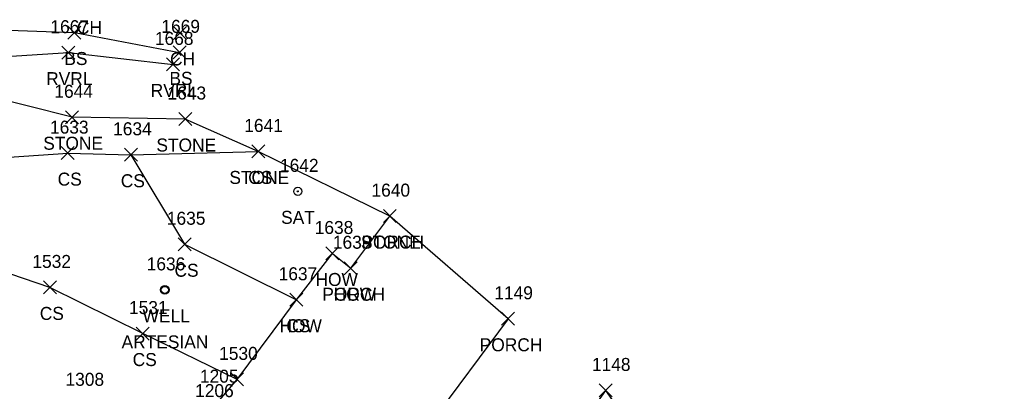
# Model space of a CAD drawing. Extents: x 1537342 to 1542195, y 163002 to 168596.
# Drawn here: x 1541938.8 to 1542089.8, y 163294.7 to 163351.9 of the extents above; entities that cross this region are included whole.
import ezdxf

# ---------------------------------------------------------------- set-up
doc = ezdxf.new("R2010")
doc.units = 0
for name, color, linetype in [('L_A', 7, 'Continuous'), ('L_I', 7, 'Continuous'), ('L_TIC', 7, 'Continuous'), ('LANT', 7, 'Continuous'), ('LASF', 7, 'Continuous'), ('LAWA', 7, 'Continuous'), ('LAWE', 7, 'Continuous'), ('LBC', 7, 'Continuous'), ('LBF', 7, 'Continuous'), ('LELB', 7, 'Continuous'), ('R_I', 7, 'Continuous'), ('U_A', 7, 'Continuous'), ('U_C', 7, 'Continuous'), ('U_I', 7, 'Continuous'), ('UWW', 7, 'Continuous')]:
    doc.layers.add(name, color=color, linetype=linetype)

msp = doc.modelspace()

# ---------------------------------------------------------------- linework, layer by layer
at = {"layer": 'L_TIC'}
for points in [[(1541946.26, 163348.87), (1541948.26, 163350.87)], [(1541948.26, 163348.87), (1541946.26, 163350.87)], [(1541962.52, 163348.81), (1541964.52, 163350.81)], [(1541964.52, 163348.81), (1541962.52, 163350.81)], [(1541945.35, 163345.77), (1541947.35, 163347.77)], [(1541947.35, 163345.77), (1541945.35, 163347.77)], [(1541962.47, 163345.82), (1541964.47, 163347.82)], [(1541964.47, 163345.82), (1541962.47, 163347.82)], [(1541961.46, 163343.96), (1541963.46, 163345.96)], [(1541963.46, 163343.96), (1541961.46, 163345.96)], [(1541945.91, 163335.83), (1541947.91, 163337.83)], [(1541947.91, 163335.83), (1541945.91, 163337.83)], [(1541963.35, 163335.56), (1541965.35, 163337.56)], [(1541965.35, 163335.56), (1541963.35, 163337.56)], [(1541945.24, 163330.31), (1541947.24, 163332.31)], [(1541947.24, 163330.31), (1541945.24, 163332.31)], [(1541954.97, 163330.06), (1541956.97, 163332.06)], [(1541956.97, 163330.06), (1541954.97, 163332.06)], [(1541954.97, 163330.06), (1541956.97, 163332.06)], [(1541956.97, 163330.06), (1541954.97, 163332.06)], [(1541974.61, 163330.57), (1541976.61, 163332.57)], [(1541976.61, 163330.57), (1541974.61, 163332.57)], [(1541974.61, 163330.57), (1541976.61, 163332.57)], [(1541976.61, 163330.57), (1541974.61, 163332.57)], [(1541994.88, 163320.62), (1541996.88, 163322.62)], [(1541996.88, 163320.62), (1541994.88, 163322.62)], [(1541994.88, 163320.62), (1541996.88, 163322.62)], [(1541996.88, 163320.62), (1541994.88, 163322.62)], [(1541994.88, 163320.62), (1541996.88, 163322.62)], [(1541996.88, 163320.62), (1541994.88, 163322.62)], [(1541963.25, 163316.29), (1541965.25, 163318.29)], [(1541965.25, 163316.29), (1541963.25, 163318.29)], [(1541986.04, 163314.87), (1541988.04, 163316.87)], [(1541988.04, 163314.87), (1541986.04, 163316.87)], [(1541988.85, 163312.6), (1541990.85, 163314.6)], [(1541990.85, 163312.6), (1541988.85, 163314.6)], [(1541988.85, 163312.6), (1541990.85, 163314.6)], [(1541990.85, 163312.6), (1541988.85, 163314.6)], [(1541942.49, 163309.65), (1541944.49, 163311.65)], [(1541944.49, 163309.65), (1541942.49, 163311.65)], [(1541980.48, 163307.75), (1541982.48, 163309.75)], [(1541982.48, 163307.75), (1541980.48, 163309.75)], [(1541980.48, 163307.75), (1541982.48, 163309.75)], [(1541982.48, 163307.75), (1541980.48, 163309.75)], [(1542013.11, 163304.82), (1542015.11, 163306.82)], [(1542015.11, 163304.82), (1542013.11, 163306.82)], [(1542013.11, 163304.82), (1542015.11, 163306.82)], [(1542015.11, 163304.82), (1542013.11, 163306.82)], [(1541956.8, 163302.55), (1541958.8, 163304.55)], [(1541958.8, 163302.55), (1541956.8, 163304.55)], [(1541971.35, 163295.5), (1541973.35, 163297.5)], [(1541973.35, 163295.5), (1541971.35, 163297.5)], [(1541971.35, 163295.5), (1541973.35, 163297.5)], [(1541973.35, 163295.5), (1541971.35, 163297.5)], [(1541971.35, 163295.5), (1541973.35, 163297.5)], [(1541973.35, 163295.5), (1541971.35, 163297.5)], [(1542028.16, 163293.8), (1542030.16, 163295.8)], [(1542030.16, 163293.8), (1542028.16, 163295.8)], [(1542028.16, 163293.8), (1542030.16, 163295.8)], [(1542030.16, 163293.8), (1542028.16, 163295.8)]]:
    msp.add_lwpolyline(points, dxfattribs=at)
at = {"layer": 'LANT'}
for radius in [0.625, 0.0833]:
    msp.add_circle((1541981.69, 163325.43), radius, dxfattribs=at)
at = {"layer": 'LASF'}
msp.add_lwpolyline([(1541995.88, 163321.62), (1541975.61, 163331.57), (1541964.35, 163336.56), (1541946.91, 163336.83), (1541932.97, 163340.32), (1541930.29, 163345.76)], dxfattribs=at)
at = {"layer": 'LAWA'}
msp.add_lwpolyline([(1542191.37, 163069.26), (1542155.13, 163097.46), (1542123.95, 163126.28), (1542083.78, 163159.16), (1542082.85, 163172.31), (1542083.05, 163192.11), (1542078.54, 163207.24), (1542059.97, 163213.12), (1542055.91, 163226.6), (1542055.2, 163251.61), (1542037.65, 163282.73), (1542029.16, 163294.8)], dxfattribs=at)
at = {"layer": 'LAWE'}
msp.add_lwpolyline([(1541842.54, 163329.29), (1541847.22, 163332.13), (1541859.96, 163336.54), (1541870, 163336.59), (1541887.85, 163336.83), (1541901.96, 163338.24), (1541917.84, 163343.33), (1541930.29, 163345.76), (1541946.35, 163346.77), (1541962.46, 163344.96)], dxfattribs=at)
at = {"layer": 'LBC'}
msp.add_lwpolyline([(1541972.35, 163296.5), (1541981.48, 163308.75), (1541987.04, 163315.87), (1541989.85, 163313.6)], dxfattribs=at)
at = {"layer": 'LBF'}
for points in [[(1541989.85, 163313.6), (1541995.88, 163321.62)], [(1542014.11, 163305.82), (1541995.88, 163321.62)], [(1542014.11, 163305.82), (1542002.07, 163289.62), (1542001.76, 163289.13), (1541998.81, 163285.26), (1541998.42, 163284.62), (1541994, 163278.6), (1541992.08, 163275.95), (1541981.64, 163283.71), (1541977.37, 163287.1), (1541969.38, 163292.99), (1541972.35, 163296.5)]]:
    msp.add_lwpolyline(points, dxfattribs=at)
at = {"layer": 'LELB'}
for points in [[(1541832.78, 163328.58), (1541834.66, 163331.5), (1541843.37, 163333.29), (1541847.54, 163333.68), (1541859.82, 163337.47), (1541869.67, 163337.89), (1541886.33, 163340.17), (1541900.15, 163345.5), (1541919.09, 163347.97), (1541926.91, 163350.6), (1541947.26, 163349.87), (1541963.47, 163346.82)], [(1541920.89, 163325.49), (1541928.89, 163330.11), (1541946.24, 163331.31), (1541955.97, 163331.06), (1541975.61, 163331.57)], [(1541955.97, 163331.06), (1541964.25, 163317.29), (1541981.48, 163308.75)], [(1541972.35, 163296.5), (1541957.8, 163303.55), (1541943.49, 163310.65), (1541929.14, 163315.52)], [(1542027.3, 163242.93), (1542035.27, 163248.44), (1542016.36, 163265.74), (1542014.6, 163273.95), (1542021.5, 163283.96), (1542029.16, 163294.8)]]:
    msp.add_lwpolyline(points, dxfattribs=at)
at = {"layer": 'UWW'}
for radius in [0.667, 0.625, 0.583, 0.542]:
    msp.add_circle((1541961.2, 163310.27), radius, dxfattribs=at)

# ---------------------------------------------------------------- texts
at = {"layer": 'L_A'}
for s, p in [('CH', (1541947.65, 163349.65)), ('BS', (1541945.7, 163344.87)), ('CH', (1541962.01, 163344.81)), ('RVRL', (1541942.91, 163341.77)), ('BS', (1541961.91, 163341.82)), ('RVRL', (1541959.02, 163339.96)), ('STONE', (1541942.46, 163331.83)), ('STONE', (1541959.9, 163331.56)), ('STONE', (1541971.15, 163326.57)), ('CS', (1541974.05, 163326.57)), ('CS', (1541944.68, 163326.31)), ('CS', (1541954.41, 163326.06)), ('CS', (1541954.41, 163326.06)), ('SAT', (1541979.12, 163320.43)), ('STONE', (1541991.42, 163316.62)), ('PORCH', (1541991.5, 163316.62)), ('PORCH', (1541991.5, 163316.62)), ('CS', (1541962.69, 163312.29)), ('HOW', (1541984.42, 163310.87)), ('PORCH', (1541985.47, 163308.6)), ('HOW', (1541987.23, 163308.6)), ('CS', (1541941.93, 163305.65)), ('HOW', (1541978.87, 163303.75)), ('CS', (1541979.92, 163303.75)), ('PORCH', (1542009.73, 163300.82)), ('PORCH', (1542009.73, 163300.82)), ('CS', (1541956.24, 163298.55))]:
    msp.add_text(s, height=2, dxfattribs=at).set_placement(p)
at = {"layer": 'L_I'}
for s, p in [('1667', (1541943.56, 163349.77)), ('1669', (1541960.67, 163349.82)), ('1668', (1541959.67, 163347.96)), ('1644', (1541944.17, 163339.83)), ('1643', (1541961.61, 163339.56)), ('1633', (1541943.5, 163334.31)), ('1634', (1541953.23, 163334.06)), ('1634', (1541953.23, 163334.06)), ('1641', (1541973.44, 163334.57)), ('1641', (1541973.44, 163334.57)), ('1642', (1541978.95, 163328.43)), ('1640', (1541993.05, 163324.62)), ('1640', (1541993.05, 163324.62)), ('1640', (1541993.05, 163324.62)), ('1635', (1541961.51, 163320.29)), ('1638', (1541984.3, 163318.87)), ('1639', (1541987.1, 163316.6)), ('1639', (1541987.1, 163316.6)), ('1532', (1541940.79, 163313.65)), ('1637', (1541978.74, 163311.75)), ('1637', (1541978.74, 163311.75)), ('1149', (1542011.98, 163308.82)), ('1149', (1542011.98, 163308.82)), ('1531', (1541955.68, 163306.55)), ('1530', (1541969.57, 163299.5)), ('1530', (1541969.57, 163299.5)), ('1530', (1541969.57, 163299.5)), ('1148', (1542027.03, 163297.8)), ('1148', (1542027.03, 163297.8)), ('1205', (1541966.61, 163295.99)), ('1206', (1541965.87, 163293.77))]:
    msp.add_text(s, height=2, dxfattribs=at).set_placement(p)
at = {"layer": 'R_I'}
msp.add_text('1308', height=2, dxfattribs=at).set_placement((1541945.89, 163295.51))
at = {"layer": 'U_A'}
msp.add_text('WELL', height=2, dxfattribs=at).set_placement((1541957.77, 163305.27))
at = {"layer": 'U_C'}
msp.add_text('ARTESIAN', height=2, dxfattribs=at).set_placement((1541954.53, 163301.27))
at = {"layer": 'U_I'}
msp.add_text('1636', height=2, dxfattribs=at).set_placement((1541958.4, 163313.27))

doc.saveas('drawing.dxf')
